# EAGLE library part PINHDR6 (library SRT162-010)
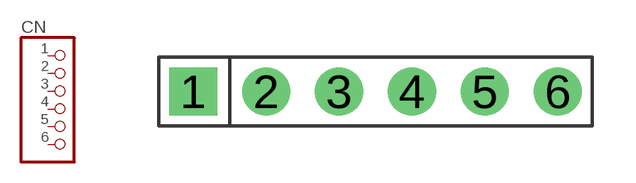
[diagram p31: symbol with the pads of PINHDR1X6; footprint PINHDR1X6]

Designator prefix CN

## PINHDR6  [PINHDR1X6]
1  1  pas
2  2  pas
3  3  pas
4  4  pas
5  5  pas
6  6  pas

## Footprint PINHDR1X6 (pad centres in mm)
drill 1.1 pad 1.676 square: 1 -6.35,0
drill 1.1 pad 1.676 round: 2 -3.81,0; 3 -1.27,0; 4 1.27,0; 5 3.81,0; 6 6.35,0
